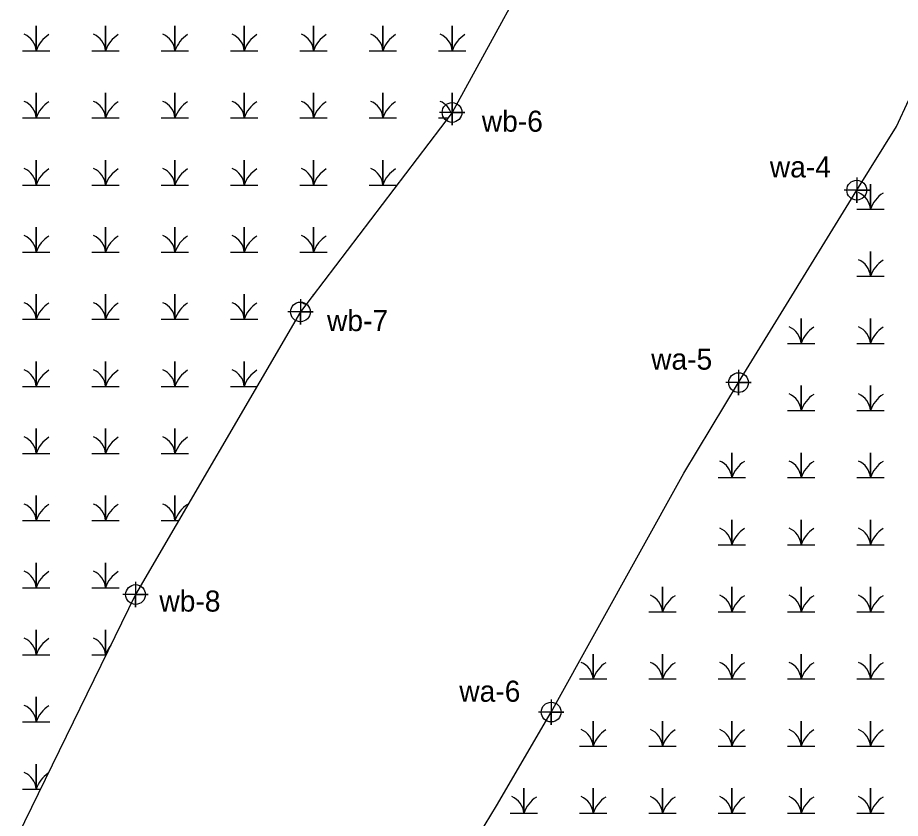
# Model space of a CAD drawing. Extents: x 2379288 to 2381905, y 330670 to 333511.
# Drawn here: x 2380102.3 to 2380311.8, y 331976.8 to 332166.7 of the extents above; entities that cross this region are included whole.
import ezdxf

# ---------------------------------------------------------------- set-up
doc = ezdxf.new("R2010")
doc.units = 0
for name, color, linetype in [('Exist Environmental Wetland Boundary', 7, 'Continuous'), ('Exist Environmental Wetland Boundary Cogo Number', 7, 'Continuous'), ('Exist Environmental Wetland Boundary Cogo Point CELL', 7, 'Continuous'), ('Exist Hydro Swamp or Marsh', 7, 'Continuous')]:
    doc.layers.add(name, color=color, linetype=linetype)

msp = doc.modelspace()

# ---------------------------------------------------------------- linework, layer by layer
at = {"layer": 'Exist Environmental Wetland Boundary'}
for points in [[(2380163.11, 332355.2), (2380184.84, 332330.77), (2380227.89, 332300.41), (2380296.91, 332269.82), (2380305.5, 332258.75), (2380302.34, 332239.07), (2380285.95, 332248.56), (2380269.29, 332243.14), (2380243.15, 332225.62), (2380230.67, 332190.32), (2380205.4, 332144.24), (2380169.42, 332096.94), (2380130.29, 332029.9), (2380102.32, 331972.59)], [(2380190.43, 331937.74), (2380215.91, 331979.8), (2380228.91, 332002.01), (2380260.36, 332058.66), (2380273.37, 332080.17), (2380301.41, 332125.81), (2380310.82, 332140.92), (2380328.42, 332178.94), (2380338.55, 332196.72), (2380340.11, 332203.44), (2380335.84, 332213), (2380327.12, 332226.26), (2380352.5, 332245.53), (2380361.25, 332251.56), (2380391.69, 332242.92), (2380420.68, 332229.92), (2380441.85, 332208.47), (2380413.47, 332149.9), (2380414.24, 332071.02), (2380410.1, 331991.07)]]:
    msp.add_lwpolyline(points, dxfattribs=at)
at = {"layer": 'Exist Environmental Wetland Boundary Cogo Point CELL'}
for points in [[(2380205.4, 332147.24), (2380205.4, 332141.24), (2380205.4, 332144.24), (2380208.4, 332144.24), (2380202.4, 332144.24)], [(2380301.41, 332128.81), (2380301.41, 332122.81), (2380301.41, 332125.81), (2380304.41, 332125.81), (2380298.41, 332125.81)], [(2380169.42, 332099.94), (2380169.42, 332093.94), (2380169.42, 332096.94), (2380172.42, 332096.94), (2380166.42, 332096.94)], [(2380273.37, 332083.17), (2380273.37, 332077.17), (2380273.37, 332080.17), (2380276.37, 332080.17), (2380270.37, 332080.17)], [(2380130.29, 332032.9), (2380130.29, 332026.9), (2380130.29, 332029.9), (2380133.29, 332029.9), (2380127.29, 332029.9)], [(2380228.91, 332005.01), (2380228.91, 331999.01), (2380228.91, 332002.01), (2380231.91, 332002.01), (2380225.91, 332002.01)]]:
    msp.add_lwpolyline(points, dxfattribs=at)
for centre in [(2380205.4, 332144.24), (2380301.41, 332125.81), (2380169.42, 332096.94), (2380273.37, 332080.17), (2380130.29, 332029.9), (2380228.91, 332002.01)]:
    msp.add_circle(centre, 2.34, dxfattribs=at)
at = {"layer": 'Exist Hydro Swamp or Marsh'}
msp.add_line((2380202.21, 332142.94), (2380204.41, 332142.94), dxfattribs=at)
for points in [[(2380103.51, 332158.86), (2380106.73, 332158.86), (2380106.73, 332164.78), (2380106.73, 332158.86), (2380109.96, 332158.86)], [(2380119.96, 332158.86), (2380123.18, 332158.86), (2380123.18, 332164.78), (2380123.18, 332158.86), (2380126.41, 332158.86)], [(2380136.41, 332158.86), (2380139.64, 332158.86), (2380139.64, 332164.78), (2380139.64, 332158.86), (2380142.86, 332158.86)], [(2380152.86, 332158.86), (2380156.09, 332158.86), (2380156.09, 332164.78), (2380156.09, 332158.86), (2380159.31, 332158.86)], [(2380169.31, 332158.86), (2380172.54, 332158.86), (2380172.54, 332164.78), (2380172.54, 332158.86), (2380175.76, 332158.86)], [(2380185.76, 332158.86), (2380188.99, 332158.86), (2380188.99, 332164.78), (2380188.99, 332158.86), (2380192.21, 332158.86)], [(2380202.21, 332158.86), (2380205.44, 332158.86), (2380205.44, 332164.78), (2380205.44, 332158.86), (2380208.67, 332158.86)], [(2380103.51, 332142.94), (2380106.73, 332142.94), (2380106.73, 332148.86), (2380106.73, 332142.94), (2380109.96, 332142.94)], [(2380119.96, 332142.94), (2380123.18, 332142.94), (2380123.18, 332148.86), (2380123.18, 332142.94), (2380126.41, 332142.94)], [(2380136.41, 332142.94), (2380139.64, 332142.94), (2380139.64, 332148.86), (2380139.64, 332142.94), (2380142.86, 332142.94)], [(2380152.86, 332142.94), (2380156.09, 332142.94), (2380156.09, 332148.86), (2380156.09, 332142.94), (2380159.31, 332142.94)], [(2380169.31, 332142.94), (2380172.54, 332142.94), (2380172.54, 332148.86), (2380172.54, 332142.94), (2380175.76, 332142.94)], [(2380185.76, 332142.94), (2380188.99, 332142.94), (2380188.99, 332148.86), (2380188.99, 332142.94), (2380192.21, 332142.94)], [(2380205.44, 332144.31), (2380205.44, 332148.86), (2380205.44, 332144.31)], [(2380103.51, 332127.02), (2380106.73, 332127.02), (2380106.73, 332132.94), (2380106.73, 332127.02), (2380109.96, 332127.02)], [(2380119.96, 332127.02), (2380123.18, 332127.02), (2380123.18, 332132.94), (2380123.18, 332127.02), (2380126.41, 332127.02)], [(2380136.41, 332127.02), (2380139.64, 332127.02), (2380139.64, 332132.94), (2380139.64, 332127.02), (2380142.86, 332127.02)], [(2380152.86, 332127.02), (2380156.09, 332127.02), (2380156.09, 332132.94), (2380156.09, 332127.02), (2380159.31, 332127.02)], [(2380169.31, 332127.02), (2380172.54, 332127.02), (2380172.54, 332132.94), (2380172.54, 332127.02), (2380175.76, 332127.02)], [(2380185.76, 332127.02), (2380188.99, 332127.02), (2380188.99, 332132.94), (2380188.99, 332127.02), (2380192.21, 332127.02)], [(2380301.45, 332121.29), (2380304.67, 332121.29), (2380304.67, 332127.21), (2380304.67, 332121.29), (2380307.9, 332121.29)], [(2380103.51, 332111.11), (2380106.73, 332111.11), (2380106.73, 332117.02), (2380106.73, 332111.11), (2380109.96, 332111.11)], [(2380119.96, 332111.11), (2380123.18, 332111.11), (2380123.18, 332117.02), (2380123.18, 332111.11), (2380126.41, 332111.11)], [(2380136.41, 332111.11), (2380139.64, 332111.11), (2380139.64, 332117.02), (2380139.64, 332111.11), (2380142.86, 332111.11)], [(2380152.86, 332111.11), (2380156.09, 332111.11), (2380156.09, 332117.02), (2380156.09, 332111.11), (2380159.31, 332111.11)], [(2380169.31, 332111.11), (2380172.54, 332111.11), (2380172.54, 332117.02), (2380172.54, 332111.11), (2380175.76, 332111.11)], [(2380301.45, 332105.38), (2380304.67, 332105.38), (2380304.67, 332111.29), (2380304.67, 332105.38), (2380307.9, 332105.38)], [(2380103.51, 332095.19), (2380106.73, 332095.19), (2380106.73, 332101.11), (2380106.73, 332095.19), (2380109.96, 332095.19)], [(2380119.96, 332095.19), (2380123.18, 332095.19), (2380123.18, 332101.11), (2380123.18, 332095.19), (2380126.41, 332095.19)], [(2380136.41, 332095.19), (2380139.64, 332095.19), (2380139.64, 332101.11), (2380139.64, 332095.19), (2380142.86, 332095.19)], [(2380152.86, 332095.19), (2380156.09, 332095.19), (2380156.09, 332101.11), (2380156.09, 332095.19), (2380159.31, 332095.19)], [(2380172.54, 332101.04), (2380172.54, 332101.11), (2380172.54, 332101.04)], [(2380285, 332089.46), (2380288.22, 332089.46), (2380288.22, 332095.38), (2380288.22, 332089.46), (2380291.45, 332089.46)], [(2380301.45, 332089.46), (2380304.67, 332089.46), (2380304.67, 332095.38), (2380304.67, 332089.46), (2380307.9, 332089.46)], [(2380103.51, 332079.27), (2380106.73, 332079.27), (2380106.73, 332085.19), (2380106.73, 332079.27), (2380109.96, 332079.27)], [(2380119.96, 332079.27), (2380123.18, 332079.27), (2380123.18, 332085.19), (2380123.18, 332079.27), (2380126.41, 332079.27)], [(2380136.41, 332079.27), (2380139.64, 332079.27), (2380139.64, 332085.19), (2380139.64, 332079.27), (2380142.86, 332079.27)], [(2380152.86, 332079.27), (2380156.09, 332079.27), (2380156.09, 332085.19), (2380156.09, 332079.27), (2380159.11, 332079.27)], [(2380285, 332073.54), (2380288.22, 332073.54), (2380288.22, 332079.46), (2380288.22, 332073.54), (2380291.45, 332073.54)], [(2380301.45, 332073.54), (2380304.67, 332073.54), (2380304.67, 332079.46), (2380304.67, 332073.54), (2380307.9, 332073.54)], [(2380103.51, 332063.35), (2380106.73, 332063.35), (2380106.73, 332069.27), (2380106.73, 332063.35), (2380109.96, 332063.35)], [(2380119.96, 332063.35), (2380123.18, 332063.35), (2380123.18, 332069.27), (2380123.18, 332063.35), (2380126.41, 332063.35)], [(2380136.41, 332063.35), (2380139.64, 332063.35), (2380139.64, 332069.27), (2380139.64, 332063.35), (2380142.86, 332063.35)], [(2380268.54, 332057.62), (2380271.77, 332057.62), (2380271.77, 332063.54), (2380271.77, 332057.62), (2380275, 332057.62)], [(2380285, 332057.62), (2380288.22, 332057.62), (2380288.22, 332063.54), (2380288.22, 332057.62), (2380291.45, 332057.62)], [(2380301.45, 332057.62), (2380304.67, 332057.62), (2380304.67, 332063.54), (2380304.67, 332057.62), (2380307.9, 332057.62)], [(2380103.51, 332047.44), (2380106.73, 332047.44), (2380106.73, 332053.35), (2380106.73, 332047.44), (2380109.96, 332047.44)], [(2380119.96, 332047.44), (2380123.18, 332047.44), (2380123.18, 332053.35), (2380123.18, 332047.44), (2380126.41, 332047.44)], [(2380136.41, 332047.44), (2380139.64, 332047.44), (2380139.64, 332053.35), (2380139.64, 332047.44), (2380140.53, 332047.44)], [(2380268.54, 332041.7), (2380271.77, 332041.7), (2380271.77, 332047.62), (2380271.77, 332041.7), (2380275, 332041.7)], [(2380285, 332041.7), (2380288.22, 332041.7), (2380288.22, 332047.62), (2380288.22, 332041.7), (2380291.45, 332041.7)], [(2380301.45, 332041.7), (2380304.67, 332041.7), (2380304.67, 332047.62), (2380304.67, 332041.7), (2380307.9, 332041.7)], [(2380103.51, 332031.52), (2380106.73, 332031.52), (2380106.73, 332037.44), (2380106.73, 332031.52), (2380109.96, 332031.52)], [(2380119.96, 332031.52), (2380123.18, 332031.52), (2380123.18, 332037.44), (2380123.18, 332031.52), (2380126.41, 332031.52)], [(2380252.09, 332025.79), (2380255.32, 332025.79), (2380255.32, 332031.7), (2380255.32, 332025.79), (2380258.54, 332025.79)], [(2380268.54, 332025.79), (2380271.77, 332025.79), (2380271.77, 332031.7), (2380271.77, 332025.79), (2380275, 332025.79)], [(2380285, 332025.79), (2380288.22, 332025.79), (2380288.22, 332031.7), (2380288.22, 332025.79), (2380291.45, 332025.79)], [(2380301.45, 332025.79), (2380304.67, 332025.79), (2380304.67, 332031.7), (2380304.67, 332025.79), (2380307.9, 332025.79)], [(2380103.51, 332015.6), (2380106.73, 332015.6), (2380106.73, 332021.52), (2380106.73, 332015.6), (2380109.96, 332015.6)], [(2380119.96, 332015.6), (2380123.18, 332015.6), (2380123.18, 332021.52), (2380123.18, 332015.6), (2380123.31, 332015.6)], [(2380235.64, 332009.87), (2380238.87, 332009.87), (2380238.87, 332015.79), (2380238.87, 332009.87), (2380242.09, 332009.87)], [(2380252.09, 332009.87), (2380255.32, 332009.87), (2380255.32, 332015.79), (2380255.32, 332009.87), (2380258.54, 332009.87)], [(2380268.54, 332009.87), (2380271.77, 332009.87), (2380271.77, 332015.79), (2380271.77, 332009.87), (2380275, 332009.87)], [(2380285, 332009.87), (2380288.22, 332009.87), (2380288.22, 332015.79), (2380288.22, 332009.87), (2380291.45, 332009.87)], [(2380301.45, 332009.87), (2380304.67, 332009.87), (2380304.67, 332015.79), (2380304.67, 332009.87), (2380307.9, 332009.87)], [(2380103.51, 331999.68), (2380106.73, 331999.68), (2380106.73, 332005.6), (2380106.73, 331999.68), (2380109.96, 331999.68)], [(2380235.64, 331993.95), (2380238.87, 331993.95), (2380238.87, 331999.87), (2380238.87, 331993.95), (2380242.09, 331993.95)], [(2380252.09, 331993.95), (2380255.32, 331993.95), (2380255.32, 331999.87), (2380255.32, 331993.95), (2380258.54, 331993.95)], [(2380268.54, 331993.95), (2380271.77, 331993.95), (2380271.77, 331999.87), (2380271.77, 331993.95), (2380275, 331993.95)], [(2380285, 331993.95), (2380288.22, 331993.95), (2380288.22, 331999.87), (2380288.22, 331993.95), (2380291.45, 331993.95)], [(2380301.45, 331993.95), (2380304.67, 331993.95), (2380304.67, 331999.87), (2380304.67, 331993.95), (2380307.9, 331993.95)], [(2380103.51, 331983.76), (2380106.73, 331983.76), (2380106.73, 331989.68), (2380106.73, 331983.76), (2380107.77, 331983.76)], [(2380219.19, 331978.03), (2380222.42, 331978.03), (2380222.42, 331983.95), (2380222.42, 331978.03), (2380225.64, 331978.03)], [(2380235.64, 331978.03), (2380238.87, 331978.03), (2380238.87, 331983.95), (2380238.87, 331978.03), (2380242.09, 331978.03)], [(2380252.09, 331978.03), (2380255.32, 331978.03), (2380255.32, 331983.95), (2380255.32, 331978.03), (2380258.54, 331978.03)], [(2380268.54, 331978.03), (2380271.77, 331978.03), (2380271.77, 331983.95), (2380271.77, 331978.03), (2380275, 331978.03)], [(2380285, 331978.03), (2380288.22, 331978.03), (2380288.22, 331983.95), (2380288.22, 331978.03), (2380291.45, 331978.03)], [(2380301.45, 331978.03), (2380304.67, 331978.03), (2380304.67, 331983.95), (2380304.67, 331978.03), (2380307.9, 331978.03)]]:
    msp.add_lwpolyline(points, dxfattribs=at)
for centre, radius, start, end in [((2380102.13, 332158.53), 4.61, 4.1403, 67.535), ((2380113.57, 332156.59), 7.21, 122.1274, 161.6222), ((2380118.58, 332158.53), 4.61, 4.1403, 67.535), ((2380130.02, 332156.59), 7.21, 122.1274, 161.6222), ((2380135.04, 332158.53), 4.61, 4.1403, 67.535), ((2380146.48, 332156.59), 7.21, 122.1274, 161.6222), ((2380151.49, 332158.53), 4.61, 4.1403, 67.535), ((2380162.93, 332156.59), 7.21, 122.1274, 161.6222), ((2380167.94, 332158.53), 4.61, 4.1403, 67.535), ((2380179.38, 332156.59), 7.21, 122.1274, 161.6222), ((2380184.39, 332158.53), 4.61, 4.1403, 67.535), ((2380195.83, 332156.59), 7.21, 122.1274, 161.6222), ((2380200.84, 332158.53), 4.61, 4.1403, 67.535), ((2380212.28, 332156.59), 7.21, 122.1274, 161.6222), ((2380102.13, 332142.61), 4.61, 4.1403, 67.535), ((2380113.57, 332140.67), 7.21, 122.1274, 161.6222), ((2380118.58, 332142.61), 4.61, 4.1403, 67.535), ((2380130.02, 332140.67), 7.21, 122.1274, 161.6222), ((2380135.04, 332142.61), 4.61, 4.1403, 67.535), ((2380146.48, 332140.67), 7.21, 122.1274, 161.6222), ((2380151.49, 332142.61), 4.61, 4.1403, 67.535), ((2380162.93, 332140.67), 7.21, 122.1274, 161.6222), ((2380167.94, 332142.61), 4.61, 4.1403, 67.535), ((2380179.38, 332140.67), 7.21, 122.1274, 161.6222), ((2380184.39, 332142.61), 4.61, 4.1403, 67.535), ((2380195.83, 332140.67), 7.21, 122.1274, 161.6222), ((2380200.84, 332142.61), 4.61, 17.7756, 67.535), ((2380102.13, 332126.69), 4.61, 4.1403, 67.535), ((2380113.57, 332124.75), 7.21, 122.1274, 161.6222), ((2380118.58, 332126.69), 4.61, 4.1403, 67.535), ((2380130.02, 332124.75), 7.21, 122.1274, 161.6222), ((2380135.04, 332126.69), 4.61, 4.1403, 67.535), ((2380146.48, 332124.75), 7.21, 122.1274, 161.6222), ((2380151.49, 332126.69), 4.61, 4.1403, 67.535), ((2380162.93, 332124.75), 7.21, 122.1274, 161.6222), ((2380167.94, 332126.69), 4.61, 4.1403, 67.535), ((2380179.38, 332124.75), 7.21, 122.1274, 161.6222), ((2380184.39, 332126.69), 4.61, 4.1403, 67.535), ((2380195.83, 332124.75), 7.21, 122.1274, 161.6222), ((2380300.07, 332120.96), 4.61, 4.1403, 67.535), ((2380311.51, 332119.02), 7.21, 122.1274, 161.6222), ((2380102.13, 332110.77), 4.61, 4.1403, 67.535), ((2380113.57, 332108.83), 7.21, 122.1274, 161.6222), ((2380118.58, 332110.77), 4.61, 4.1403, 67.535), ((2380130.02, 332108.83), 7.21, 122.1274, 161.6222), ((2380135.04, 332110.77), 4.61, 4.1403, 67.535), ((2380146.48, 332108.83), 7.21, 122.1274, 161.6222), ((2380151.49, 332110.77), 4.61, 4.1403, 67.535), ((2380162.93, 332108.83), 7.21, 122.1274, 161.6222), ((2380167.94, 332110.77), 4.61, 4.1403, 67.535), ((2380179.38, 332108.83), 7.21, 122.1274, 161.6222), ((2380300.07, 332105.04), 4.61, 4.1403, 67.535), ((2380311.51, 332103.1), 7.21, 122.1274, 161.6222), ((2380102.13, 332094.86), 4.61, 4.1403, 67.535), ((2380113.57, 332092.92), 7.21, 122.1274, 161.6222), ((2380118.58, 332094.86), 4.61, 4.1403, 67.535), ((2380130.02, 332092.92), 7.21, 122.1274, 161.6222), ((2380135.04, 332094.86), 4.61, 4.1403, 67.535), ((2380146.48, 332092.92), 7.21, 122.1274, 161.6222), ((2380151.49, 332094.86), 4.61, 4.1403, 67.535), ((2380162.93, 332092.92), 7.21, 122.1274, 161.6222), ((2380167.94, 332094.86), 4.61, 53.7511, 67.535), ((2380283.62, 332089.13), 4.61, 4.1403, 67.535), ((2380295.06, 332087.19), 7.21, 122.1274, 161.6222), ((2380300.07, 332089.13), 4.61, 4.1403, 67.535), ((2380311.51, 332087.19), 7.21, 122.1274, 161.6222), ((2380102.13, 332078.94), 4.61, 4.1403, 67.535), ((2380113.57, 332077), 7.21, 122.1274, 161.6222), ((2380118.58, 332078.94), 4.61, 4.1403, 67.535), ((2380130.02, 332077), 7.21, 122.1274, 161.6222), ((2380135.04, 332078.94), 4.61, 4.1403, 67.535), ((2380146.48, 332077), 7.21, 122.1274, 161.6222), ((2380151.49, 332078.94), 4.61, 4.1403, 67.535), ((2380162.93, 332077), 7.21, 122.1274, 161.6222), ((2380283.62, 332073.21), 4.61, 4.1403, 67.535), ((2380295.06, 332071.27), 7.21, 122.1274, 161.6222), ((2380300.07, 332073.21), 4.61, 4.1403, 67.535), ((2380311.51, 332071.27), 7.21, 122.1274, 161.6222), ((2380102.13, 332063.02), 4.61, 4.1403, 67.535), ((2380113.57, 332061.08), 7.21, 122.1274, 161.6222), ((2380118.58, 332063.02), 4.61, 4.1403, 67.535), ((2380130.02, 332061.08), 7.21, 122.1274, 161.6222), ((2380135.04, 332063.02), 4.61, 4.1403, 67.535), ((2380146.48, 332061.08), 7.21, 122.1274, 161.6222), ((2380267.17, 332057.29), 4.61, 4.1403, 67.535), ((2380278.61, 332055.35), 7.21, 122.1274, 161.6222), ((2380283.62, 332057.29), 4.61, 4.1403, 67.535), ((2380295.06, 332055.35), 7.21, 122.1274, 161.6222), ((2380300.07, 332057.29), 4.61, 4.1403, 67.535), ((2380311.51, 332055.35), 7.21, 122.1274, 161.6222), ((2380102.13, 332047.1), 4.61, 4.1403, 67.535), ((2380113.57, 332045.16), 7.21, 122.1274, 161.6222), ((2380118.58, 332047.1), 4.61, 4.1403, 67.535), ((2380130.02, 332045.16), 7.21, 122.1274, 161.6222), ((2380135.04, 332047.1), 4.61, 4.1403, 67.535), ((2380146.48, 332045.16), 7.21, 122.1274, 161.6222), ((2380267.17, 332041.37), 4.61, 4.1403, 67.535), ((2380278.61, 332039.43), 7.21, 122.1274, 161.6222), ((2380283.62, 332041.37), 4.61, 4.1403, 67.535), ((2380295.06, 332039.43), 7.21, 122.1274, 161.6222), ((2380300.07, 332041.37), 4.61, 4.1403, 67.535), ((2380311.51, 332039.43), 7.21, 122.1274, 161.6222), ((2380102.13, 332031.18), 4.61, 4.1403, 67.535), ((2380113.57, 332029.25), 7.21, 122.1274, 161.6222), ((2380118.58, 332031.18), 4.61, 4.1403, 67.535), ((2380130.02, 332029.25), 7.21, 122.1274, 161.6222), ((2380250.72, 332025.45), 4.61, 4.1403, 67.535), ((2380262.16, 332023.51), 7.21, 122.1274, 161.6222), ((2380267.17, 332025.45), 4.61, 4.1403, 67.535), ((2380278.61, 332023.51), 7.21, 122.1274, 161.6222), ((2380283.62, 332025.45), 4.61, 4.1403, 67.535), ((2380295.06, 332023.51), 7.21, 122.1274, 161.6222), ((2380300.07, 332025.45), 4.61, 4.1403, 67.535), ((2380311.51, 332023.51), 7.21, 122.1274, 161.6222), ((2380102.13, 332015.27), 4.61, 4.1403, 67.535), ((2380113.57, 332013.33), 7.21, 122.1274, 161.6222), ((2380118.58, 332015.27), 4.61, 4.1403, 67.535), ((2380130.02, 332013.33), 7.21, 141.1097, 161.6222), ((2380234.27, 332009.54), 4.61, 4.1403, 67.535), ((2380245.71, 332007.6), 7.21, 122.1274, 161.6222), ((2380250.72, 332009.54), 4.61, 4.1403, 67.535), ((2380262.16, 332007.6), 7.21, 122.1274, 161.6222), ((2380267.17, 332009.54), 4.61, 4.1403, 67.535), ((2380278.61, 332007.6), 7.21, 122.1274, 161.6222), ((2380283.62, 332009.54), 4.61, 4.1403, 67.535), ((2380295.06, 332007.6), 7.21, 122.1274, 161.6222), ((2380300.07, 332009.54), 4.61, 4.1403, 67.535), ((2380311.51, 332007.6), 7.21, 122.1274, 161.6222), ((2380102.13, 331999.35), 4.61, 4.1403, 67.535), ((2380113.57, 331997.41), 7.21, 122.1274, 161.6222), ((2380234.27, 331993.62), 4.61, 4.1403, 67.535), ((2380245.71, 331991.68), 7.21, 122.1274, 161.6222), ((2380250.72, 331993.62), 4.61, 4.1403, 67.535), ((2380262.16, 331991.68), 7.21, 122.1274, 161.6222), ((2380267.17, 331993.62), 4.61, 4.1403, 67.535), ((2380278.61, 331991.68), 7.21, 122.1274, 161.6222), ((2380283.62, 331993.62), 4.61, 4.1403, 67.535), ((2380295.06, 331991.68), 7.21, 122.1274, 161.6222), ((2380300.07, 331993.62), 4.61, 4.1403, 67.535), ((2380311.51, 331991.68), 7.21, 122.1274, 161.6222), ((2380102.13, 331983.43), 4.61, 4.1403, 67.535), ((2380113.57, 331981.49), 7.21, 123.4333, 161.6222), ((2380217.82, 331977.7), 4.61, 4.1403, 67.535), ((2380229.26, 331975.76), 7.21, 122.1274, 161.6222), ((2380234.27, 331977.7), 4.61, 4.1403, 67.535), ((2380245.71, 331975.76), 7.21, 122.1274, 161.6222), ((2380250.72, 331977.7), 4.61, 4.1403, 67.535), ((2380262.16, 331975.76), 7.21, 122.1274, 161.6222), ((2380267.17, 331977.7), 4.61, 4.1403, 67.535), ((2380278.61, 331975.76), 7.21, 122.1274, 161.6222), ((2380283.62, 331977.7), 4.61, 4.1403, 67.535), ((2380295.06, 331975.76), 7.21, 122.1274, 161.6222), ((2380300.07, 331977.7), 4.61, 4.1403, 67.535), ((2380311.51, 331975.76), 7.21, 122.1274, 161.6222)]:
    msp.add_arc(centre, radius, start, end, dxfattribs=at)

# ---------------------------------------------------------------- texts
at = {"layer": 'Exist Environmental Wetland Boundary Cogo Number'}
for s, p in [('wb-6', (2380212.45, 332139.67)), ('wa-4', (2380280.79, 332128.83)), ('wb-7', (2380175.73, 332092.37)), ('wa-5', (2380252.63, 332083.23)), ('wb-8', (2380135.95, 332025.85)), ('wa-6', (2380207.11, 332004.47))]:
    msp.add_text(s, height=5, dxfattribs=at).set_placement(p)

doc.saveas('drawing.dxf')
